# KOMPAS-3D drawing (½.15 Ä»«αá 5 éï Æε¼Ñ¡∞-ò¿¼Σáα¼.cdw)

Views: Вид 1, Вид 2
Referenced files: Подвеска ВЧ-заградителя.cdw
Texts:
  Текст на чертеже
  Размерные надписи
  Шероховатость
  Линия-выноска #1
  Линия-выноска #2
  Линия-выноска #3
  Отклонения формы и база
  Заголовок таблицы
  Ячейка таблицы
  Стрелка вида
  Обозначение изменения
  Фигурная скобка
  Номер узла
  Марка координационной оси
  VRCB
  Выносная надпись
  Обозначение узла
  Марка/позиционное обозначение с линией-выноской
  Марка/позиционное обозначение на линии
  Марка/позиционное обозначение без линии-выноски
  ООббыыччнныыйй
  Definition Term
  Definition List
  Address
  Blockquote
  Preformatted
  Courier New
  z-Bottom of Form
  z-Top of Form
  Лит-Масса-Масштаб
  Материал-Предприятие
  Title Specification
  Body Specification ( left align )
  Body Specificaton ( centered )
  Без имени
  SPEC
  Normal
  Txt
  Body Text
  heading 1
  Знак Знак Знак Знак Знак Знак
  Verdana
  Simplex
  TXT
  txt
  MS Sans Serif
  Additional DXF text style 0
  Обычный
  Термин
  Список определений
  Адрес
  Цитаты
  Форматированный
  Z-конец формы
  Z-начало формы
  ТекстШаг1
  Title
  Денис
  header
  heading 2
  AGOpus
  footer
  NormalParagraphStyle
  Body Text 3
  ссылки
  Подпись в квадратике
  табл
  цепи
  Маркировка
  клеммы, контакты
  тексты табл
  Тексты. 3,2
  ЗОНА_привяз
  текст переноса
  ТТееррммиинн
  ССппииссоокк ооппррееддееллеенниийй
  ААддрреесс
  ЦЦииттааттыы
  ФФооррммааттиирроовваанннныыйй
  Z-ккооннеецц ффооррммыы
  Z-ннааччааллоо ффооррммыы
  GOST 2.304 type A
  rustxt
  heading 8
  heading 3
  heading 6
  heading 7
  russ
  Абзац Знак
  heading 4
  heading 5
  heading 9
  HeliosLight
  Pa3
  Pa1
  Три с половиной
  style2
  Шрифт 2.5
  Заголовки
  RUSTXT
  Table Contents
  Table Heading
  ГОСТ_МНЕ
  ESK - Обозначение
  маркировка
  ISOCP
  ROMANS
  SIMPLEX
  Обычный (веб)
  Текст 3,5
  Tahoma
  CNBNDG+TimesNewRoman
  Subtitle
  ISOCPEUR
  FR5
  romans
  Подписи
  Схема монтажа ВЧ-заградителя на опору №5.
  ВЛ-110 кВ Тюмень - Химфарм
  Примечание - примечания см. 16/01-ПОС, л.10.
  Кран КС-35719-1-02
  подписи
  CONTINUOUS_RGB_0_0_0_THICK_0.13
  GOST2.303 4_RGB_0_0_0_SC_0.04_THICK_0.13
  CONTINUOUS_RGB_0_0_0_THICK_0.18
  CONTINUOUS_RGB_173_173_173_THICK_0.13
  GOST2.303 4_RGB_173_173_173_SC_0.04_THICK_0.13
  СONTINUOUS_RGB_0_0_0_THICK_0.13
  POLYLINE_STYLE_0.30_RGB_0_0_0
  CONTINUOUS_RGB_0_0_0_THICK_0.3
  GOST2.303 6_RGB_0_0_0_SC_0.04_THICK_0.13
  POLYLINE_STYLE_0.18_RGB_0_0_0
  GOST2.303 6_RGB_0_0_0_SC_0_THICK_0.18
  K5LT_AXLED_RGB_255_128_0_SC_1_THICK_0.18
  CONTINUOUS_RGB_0_0_0_THICK_0.25
  POLYLINE_STYLE_0.21_RGB_0_0_0
  СONTINUOUS_RGB_0_0_0_THICK_0.18
  POLYLINE_STYLE_0.50_RGB_0_0_0
  POLYLINE_STYLE_0.40_RGB_0_0_0
  CONTINUOUS_RGB_0_0_0_THICK_0.6
  Стили документа
  Автомобильный кран КС-35714
  Ромин
  Подвеска ВЧ-заградителя на
  опоре №5
  Политова
  Разраб.
  Микрюков
  Схема пневматическая соединений
  Перезавод ВЛ на ПС Тюмень. Реконструкция устройств
  РЗ и ПА на обратных концах отходящих ВЛ,
  ВОЛС Тюменского ТПО
  ВЛ 110 кВ Тюмень-Химфарм
  Нов.
  ГИП
  Матвеев
Dimensions and other numbers on the sheet: 16/01-ПОС; 7; 3,2_; 3.5; 2.5; 2,5; 1,8; 3,2; 2,5 (контакты, клеммы); 3,2 (надписи); 3,2 (Зоны); 5; 2,5_01; 2,5_3; 3,5_01; 3,5_tabl; 5_заголовок; 2,3_; 3,2_зона не привяз; 3,5; 3.2 маркировка; 3,2 элементы; 3,2 линия; 3,2 таблица; 2,5 грязносинь; 2.5 курсив; 2.5_Э5_надписи; 2.5_Э5_ссылки; 2.5_кабель; 3.2; 2.5 надписи; 3 и 5; 5,0_белый_подчёркнутый; 3.2 фиол; 3.2 (текст); 24600; 10500; 4000; 6100; 4800; 12; 4; 05.14; 16/01-04-091-ЭП-; 15; 3; 253-14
